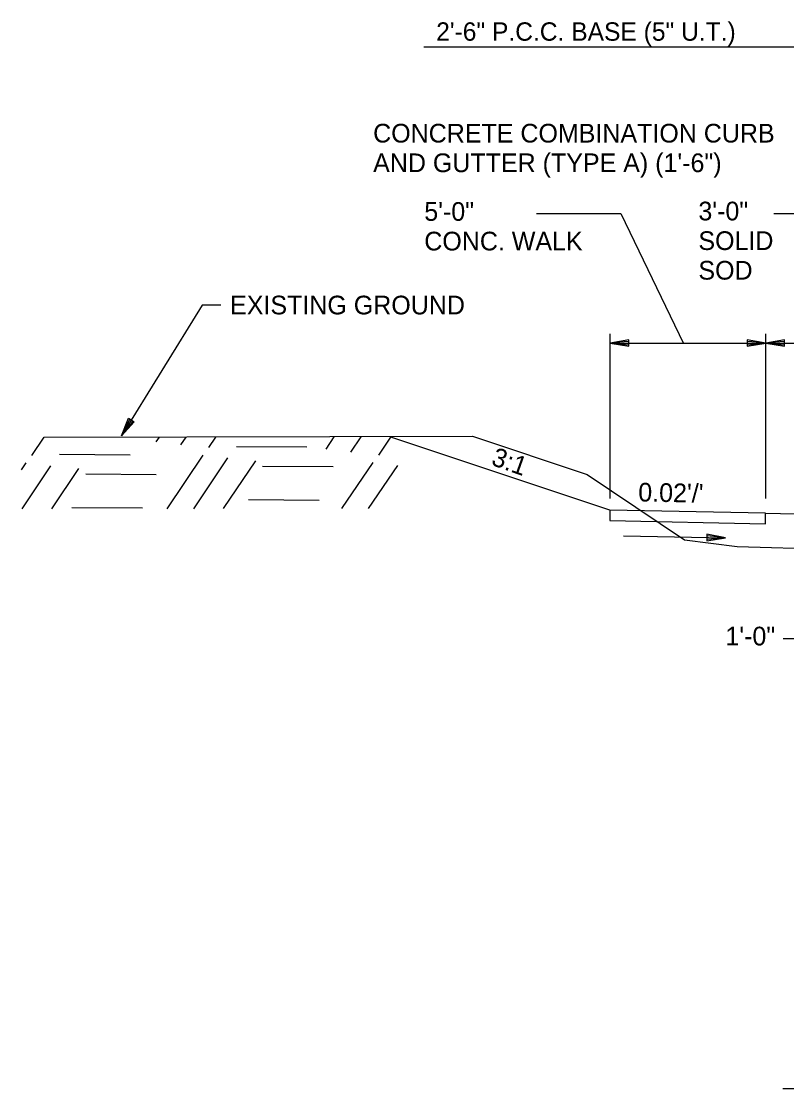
# Model space of a CAD drawing. Extents: x 1001270 to 1003428, y 1840152 to 1842912.
# Drawn here: x 1001309.11 to 1001333.67, y 1841881.27 to 1841915.52 of the extents above; entities that cross this region are included whole.
import ezdxf

# ---------------------------------------------------------------- set-up
doc = ezdxf.new("R2010")
doc.units = 0
for name, color, linetype in [('19', 7, 'Continuous'), ('20', 7, 'Continuous'), ('8', 7, 'Continuous')]:
    doc.layers.add(name, color=color, linetype=linetype)

# ---------------------------------------------------------------- blocks, each defined once
blk = doc.blocks.new('TM')
at = {"layer": '8'}
for p, q in [((-120.309, 21.181), (-119.787, -20.829)), ((0, 0), (-120.309, 21.181)), ((-31.382, 2.945), (-120.176, 10.512)), ((-119.787, -20.829), (0, 0)), ((-119.911, -10.826), (-31.307, -3.057))]:
    blk.add_line(p, q, dxfattribs=at)

msp = doc.modelspace()

# ---------------------------------------------------------------- linework, layer by layer
at = {"layer": '19'}
for p, q in [((1001322.024, 1841914.699), (1001337.502, 1841914.699)), ((1001325.638, 1841909.352), (1001328.348, 1841909.352)), ((1001328.348, 1841909.352), (1001330.362, 1841905.181)), ((1001333.253, 1841909.352), (1001333.997, 1841909.352)), ((1001328.002, 1841900.204), (1001328.002, 1841905.495)), ((1001328.602, 1841905.3), (1001328.002, 1841905.195)), ((1001328.602, 1841905.245), (1001328.162, 1841905.21)), ((1001328.602, 1841905.09), (1001328.602, 1841905.3)), ((1001332.402, 1841905.3), (1001332.402, 1841905.09)), ((1001333.002, 1841905.195), (1001332.402, 1841905.3)), ((1001332.842, 1841905.21), (1001332.402, 1841905.245)), ((1001333.002, 1841900.204), (1001333.002, 1841905.495)), ((1001333.602, 1841905.3), (1001333.002, 1841905.195)), ((1001333.602, 1841905.245), (1001333.162, 1841905.21)), ((1001333.602, 1841905.09), (1001333.602, 1841905.3)), ((1001328.002, 1841905.195), (1001337.502, 1841905.195)), ((1001328.002, 1841905.195), (1001328.602, 1841905.09)), ((1001328.162, 1841905.18), (1001328.602, 1841905.14)), ((1001332.402, 1841905.09), (1001333.002, 1841905.195)), ((1001332.402, 1841905.14), (1001332.842, 1841905.18)), ((1001333.002, 1841905.195), (1001333.602, 1841905.09)), ((1001333.162, 1841905.18), (1001333.602, 1841905.14)), ((1001312.328, 1841902.214), (1001312.551, 1841902.781)), ((1001312.729, 1841902.671), (1001312.328, 1841902.214)), ((1001312.402, 1841902.355), (1001312.595, 1841902.749)), ((1001312.688, 1841902.693), (1001312.425, 1841902.344)), ((1001312.551, 1841902.781), (1001312.729, 1841902.671)), ((1001309.452, 1841901.591), (1001309.844, 1841902.173)), ((1001313.438, 1841902.025), (1001313.544, 1841902.175)), ((1001314.233, 1841901.933), (1001314.398, 1841902.177)), ((1001315.128, 1841901.841), (1001315.354, 1841902.179)), ((1001318.892, 1841901.785), (1001319.154, 1841902.18)), ((1001319.687, 1841901.693), (1001320.018, 1841902.182)), ((1001320.582, 1841901.601), (1001320.963, 1841902.175)), ((1001327.995, 1841899.831), (1001320.963, 1841902.175)), ((1001316.016, 1841901.87), (1001318.276, 1841901.859)), ((1001310.341, 1841901.63), (1001312.601, 1841901.608)), ((1001313.79, 1841899.877), (1001314.942, 1841901.599)), ((1001314.645, 1841899.88), (1001315.737, 1841901.507)), ((1001309.113, 1841901.123), (1001309.267, 1841901.348)), ((1001309.135, 1841899.874), (1001310.061, 1841901.256)), ((1001310.09, 1841899.876), (1001310.957, 1841901.164)), ((1001315.6, 1841899.882), (1001316.632, 1841901.415)), ((1001316.846, 1841901.242), (1001319.116, 1841901.229)), ((1001319.4, 1841899.883), (1001320.396, 1841901.359)), ((1001320.255, 1841899.886), (1001321.191, 1841901.267)), ((1001311.181, 1841901), (1001313.441, 1841900.979)), ((1001316.404, 1841900.171), (1001318.663, 1841900.15)), ((1001310.728, 1841899.921), (1001312.999, 1841899.909)), ((1001332.994, 1841899.732), (1001327.995, 1841899.831)), ((1001327.995, 1841899.831), (1001327.995, 1841899.498)), ((1001327.995, 1841899.498), (1001332.994, 1841899.398)), ((1001332.994, 1841899.398), (1001332.994, 1841899.732)), ((1001332.994, 1841899.732), (1001332.994, 1841899.732)), ((1001332.994, 1841899.732), (1001335.993, 1841899.671)), ((1001333.553, 1841895.715), (1001335.002, 1841895.715)), ((1001333.553, 1841895.715), (1001335.002, 1841895.715)), ((1001333.542, 1841881.27), (1001365.91, 1841881.27))]:
    msp.add_line(p, q, dxfattribs=at)
for points in [[(1001315.511, 1841906.413), (1001314.911, 1841906.413), (1001312.328, 1841902.214)], [(1001309.844, 1841902.173), (1001323.592, 1841902.207), (1001327.269, 1841900.974)], [(1001327.269, 1841900.974), (1001330.395, 1841898.879), (1001332.076, 1841898.667), (1001335.018, 1841898.583), (1001337.723, 1841898.752), (1001349.491, 1841899.028), (1001361.502, 1841898.688), (1001365.691, 1841898.151), (1001370.572, 1841897.903), (1001374.658, 1841897.69), (1001379.373, 1841897.521), (1001388.877, 1841897.581)]]:
    msp.add_lwpolyline(points, dxfattribs=at)
at = {"layer": '20'}
msp.add_line((1001328.432, 1841899.012), (1001331.702, 1841898.947), dxfattribs=at)

# ---------------------------------------------------------------- block references
at = {"layer": '19', "xscale": 0.0050063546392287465, "yscale": 0.005006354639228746, "rotation": -1.1310771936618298}
msp.add_blockref('TM', (1001331.703, 1841898.944), dxfattribs=at)

# ---------------------------------------------------------------- texts
at = {"layer": '19'}
for s, height, p in [('2\'-6" P.C.C. BASE (5" U.T.)', 0.59001, (1001322.423, 1841914.895)), ('EXISTING GROUND', 0.6, (1001315.811, 1841906.114))]:
    msp.add_text(s, height=height, dxfattribs=at).set_placement(p)
for s, rotation, p in [('CONCRETE COMBINATION CURB', 360, (1001320.4, 1841911.628)), ('AND GUTTER (TYPE A) (1\'-6")', 360, (1001320.4, 1841910.678)), ('5\'-0"', 360, (1001322.041, 1841909.116)), ('3\'-0"', 360, (1001330.836, 1841909.13)), ('CONC. WALK', 360, (1001322.041, 1841908.166)), ('SOLID ', 360, (1001330.836, 1841908.18)), ('SOD', 360, (1001330.836, 1841907.23)), ('3:1', 340.4943, (1001324.156, 1841901.296)), ("0.02'/'", 358.8581, (1001328.902, 1841900.113)), ('1\'-0"', 360, (1001331.703, 1841895.492))]:
    msp.add_text(s, height=0.6, rotation=rotation, dxfattribs=at).set_placement(p)

doc.saveas('drawing.dxf')
